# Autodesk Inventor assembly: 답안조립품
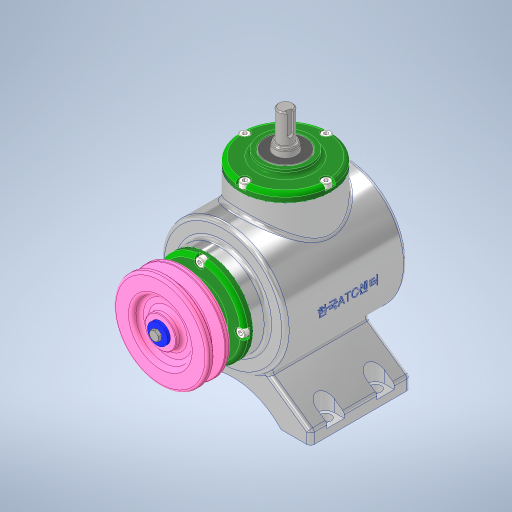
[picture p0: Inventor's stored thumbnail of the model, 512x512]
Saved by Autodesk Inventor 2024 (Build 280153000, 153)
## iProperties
Created: 2023-08
Part Number: 답안조립품
Document SubType Name: Assembly
Designer: Owner
Author: Owner
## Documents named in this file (17)
- C:\Users\Owner\Desktop\730813V1003\답안조립품.iam
- C:\Users\Owner\Desktop\730813V1003\본체.ipt
- C:\Users\Owner\Desktop\730813V1003\V-벨트풀리.ipt
- C:\Users\Owner\Desktop\730813V1003\메인 베벨기어.ipt
- C:\Users\Owner\Desktop\730813V1003\메인 축.ipt
- 메인 축.ipt
- C:\Users\Owner\Desktop\730813V1003\베어링 6203.ipt
- C:\Users\Owner\Desktop\730813V1003\볼트 M4 x 10.ipt
- C:\Users\Owner\Desktop\730813V1003\서브 베벨기어.ipt
- C:\Users\Owner\Desktop\730813V1003\서브 축.ipt
- 서브 축.ipt
- C:\Users\Owner\Desktop\730813V1003\오일실 17 x 32 x 8.ipt
- C:\Users\Owner\Desktop\730813V1003\와셔 4 x 16.ipt
- C:\Users\Owner\Desktop\730813V1003\육각볼트 M4 x 8.ipt
- C:\Users\Owner\Desktop\730813V1003\커버.ipt
- C:\Users\Owner\Desktop\730813V1003\키 4 x 4 x 14.ipt
- C:\Users\Owner\Desktop\730813V1003\키 5 x 5 x 14.ipt
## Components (1 placed, 1 different names)
1. V-벨트풀리:1
